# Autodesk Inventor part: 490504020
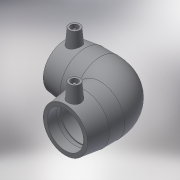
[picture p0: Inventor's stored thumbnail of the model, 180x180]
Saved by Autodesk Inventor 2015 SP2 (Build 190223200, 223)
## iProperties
Created: 2017-06
Part Number: 490504020
Material: Generic
Description: PLASSON 90° ELBOW 20
Document SubType Name: Modeling
Designer: KIM
Mass: 55.0731 g
Surface Area: 148.067 cm^2
Volume: 55.0731 cm^3
Density: 1 g/cm^3
Appearance: Default
Author: KIM
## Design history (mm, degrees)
derived "490504.ipt"
feature "Solid1::490504.ipt"
tag "TaggingFeature1"
body "Solid1"
other parameters: "d2" = 36, "d4" = 19.41176, "d5" = 32.4, "d8" = 168 deg, "d10" = 14, "d11" = 4.66667, "d14" = 17.6296, "d19" = 3.52592, "d20" = 168 deg, "d22" = 33.12, "d23" = 36, "d24" = 32.1264, "d29" = 38, "d30" = 15, "d31" = 39.6, "d34" = 5 deg, "d35" = 15, "d39" = 5 deg, "d41" = 4, "d42" = 14, "d43" = 0, "d45" = 4, "d46" = 14, "d47" = 0, "d50" = 17, "d51" = 14, "d52" = 35, "d54" = 90 deg, "d67" = 45 deg, "d71" = 90 deg, "d75" = 1.8, "d82" = 45 deg, "d83" = 35, "d84" = 32.4, "d86" = 16.2, "d87" = 90 deg, "d90" = 35, "d91" = 0, "d92" = 35, "d93" = 0, "d94" = 90 deg, "d95" = 16.56, "d98" = 66, "d101" = 3, "d102" = 0, "d103" = 3, "d104" = 0, "d105" = 10.15, "d106" = 2.5375, "d107" = 66, "d110" = 19.25, "L_" = 66, "L_1" = 35, "D_" = 36, "A_" = 38, "d_2" = 12
